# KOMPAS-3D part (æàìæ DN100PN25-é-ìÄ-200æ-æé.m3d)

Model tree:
1. Объединить компоненты:1  (labels: СЕНС DN100PN25-В-НО-200С)
2. Эскиз:1
3. Операция выдавливания:1
     Расстояние 1 = 14
4. Фаска:1
     Угол = 45; Длина 1 = 2; Длина 2 = 2

Referenced files in D:\Савин\!СЕНСОР\3D для заказчика\!Новый перечень\СЕНС\7. СЕНС-В-НО-200С\DN100\: СЕНС DN100PN25-В-НО-200С.a3d
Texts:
  СЕНС DN100PN25-В-НО-200С-СВ
  ООО НПП Сенсор
  СЕНС DN100PN25-В-НО-200С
